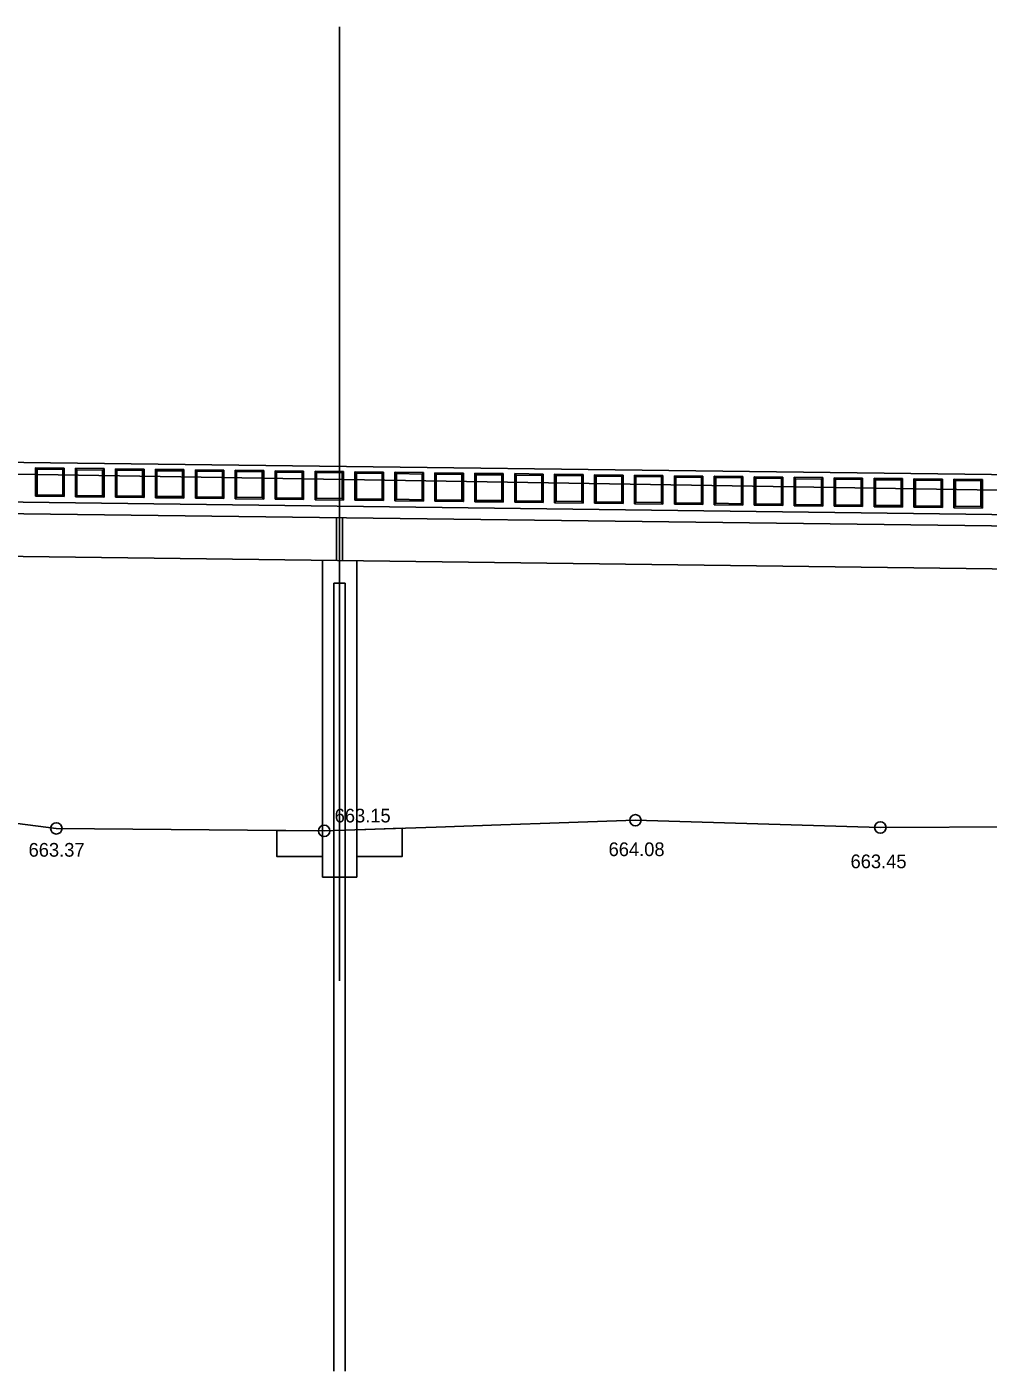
# Model space of a CAD drawing. Extents: x -845213 to 595816, y -257022 to 229056.
# Drawn here: x 595478.6 to 595562.8, y 228642.7 to 228760.5 of the extents above; entities that cross this region are included whole.
import ezdxf

# ---------------------------------------------------------------- set-up
doc = ezdxf.new("R2010")
doc.units = 0
for name, color, linetype in [('B_CL', 7, 'Continuous'), ('B_CONC', 7, 'Continuous'), ('B_CONC_HIDDEN', 7, 'Continuous'), ('B_MISC', 7, 'Continuous'), ('B_PATTERN', 7, 'Continuous'), ('B_PILES_HIDDEN', 7, 'Continuous'), ('B_SCREEN', 7, 'Continuous'), ('E_STRUCT', 7, 'Continuous'), ('P_E_PROF', 7, 'Continuous'), ('P_PROF', 7, 'Continuous')]:
    doc.layers.add(name, color=color, linetype=linetype)

msp = doc.modelspace()

# ---------------------------------------------------------------- linework, layer by layer
at = {"layer": 'B_CL'}
msp.add_line((595505.96, 228676.87), (595505.96, 228760.49), dxfattribs=at)
at = {"layer": 'B_CONC'}
for p, q in [((595399.25, 228723.31), (595719.75, 228719.29)), ((595421.62, 228718.53), (595696.95, 228715.07)), ((595505.69, 228713.72), (595505.69, 228717.47)), ((595506.23, 228713.72), (595506.23, 228717.47)), ((595417.81, 228714.82), (595700.75, 228711.28)), ((595504.46, 228687.36), (595504.46, 228713.74)), ((595507.46, 228687.45), (595507.46, 228713.7))]:
    msp.add_line(p, q, dxfattribs=at)
at = {"layer": 'B_CONC_HIDDEN'}
for p, q in [((595504.46, 228690.02), (595504.46, 228685.97)), ((595507.46, 228690.12), (595507.46, 228685.97)), ((595504.46, 228685.97), (595507.46, 228685.97))]:
    msp.add_line(p, q, dxfattribs=at)
at = {"layer": 'B_MISC'}
for centre in [(595531.89, 228690.95), (595481.13, 228690.24), (595504.61, 228690.02), (595553.36, 228690.32)]:
    msp.add_circle(centre, 0.5, dxfattribs=at)
at = {"layer": 'B_PATTERN'}
for points in [[(595507.46, 228687.79), (595507.46, 228690.12), (595511.46, 228690.25), (595511.46, 228687.79)], [(595500.46, 228690.06), (595500.46, 228687.79), (595504.46, 228687.79), (595504.46, 228690.02), (595504.46, 228690.02)]]:
    msp.add_lwpolyline(points, close=True, dxfattribs=at)
at = {"layer": 'B_PILES_HIDDEN'}
for p, q in [((595505.46, 228711.72), (595505.46, 228642.67)), ((595505.46, 228711.72), (595506.46, 228711.72)), ((595506.46, 228711.72), (595506.46, 228642.67))]:
    msp.add_line(p, q, dxfattribs=at)
at = {"layer": 'B_SCREEN'}
for p, q in [((595479.32, 228719.35), (595479.32, 228721.85)), ((595479.32, 228721.85), (595481.82, 228721.82)), ((595479.44, 228721.73), (595479.32, 228721.85)), ((595479.44, 228721.73), (595481.69, 228721.7)), ((595479.44, 228719.48), (595479.44, 228721.73)), ((595481.69, 228721.7), (595481.82, 228721.82)), ((595481.69, 228719.45), (595481.69, 228721.7)), ((595481.82, 228719.32), (595481.82, 228721.82)), ((595482.82, 228719.31), (595482.82, 228721.81)), ((595482.82, 228721.81), (595485.32, 228721.78)), ((595482.94, 228721.68), (595482.82, 228721.81)), ((595482.94, 228721.68), (595485.19, 228721.65)), ((595482.94, 228719.43), (595482.94, 228721.68)), ((595485.19, 228721.65), (595485.32, 228721.78)), ((595485.19, 228719.4), (595485.19, 228721.65)), ((595485.32, 228719.28), (595485.32, 228721.78)), ((595486.32, 228719.26), (595486.32, 228721.76)), ((595486.32, 228721.76), (595488.82, 228721.73)), ((595486.44, 228721.64), (595486.32, 228721.76)), ((595486.44, 228721.64), (595488.69, 228721.61)), ((595486.44, 228719.39), (595486.44, 228721.64)), ((595488.69, 228721.61), (595488.82, 228721.73)), ((595488.69, 228719.36), (595488.69, 228721.61)), ((595488.82, 228719.23), (595488.82, 228721.73)), ((595489.82, 228719.22), (595489.82, 228721.72)), ((595489.82, 228721.72), (595492.32, 228721.69)), ((595489.94, 228721.59), (595489.82, 228721.72)), ((595489.94, 228721.59), (595492.19, 228721.57)), ((595489.94, 228719.34), (595489.94, 228721.59)), ((595492.19, 228721.57), (595492.32, 228721.69)), ((595492.19, 228719.32), (595492.19, 228721.57)), ((595492.32, 228719.19), (595492.32, 228721.69)), ((595493.32, 228719.18), (595493.32, 228721.68)), ((595493.32, 228721.68), (595495.82, 228721.65)), ((595493.44, 228721.55), (595493.32, 228721.68)), ((595493.44, 228721.55), (595495.69, 228721.52)), ((595493.44, 228719.3), (595493.44, 228721.55)), ((595495.69, 228721.52), (595495.82, 228721.65)), ((595495.69, 228719.27), (595495.69, 228721.52)), ((595495.82, 228719.15), (595495.82, 228721.65)), ((595496.82, 228719.13), (595496.82, 228721.63)), ((595496.82, 228721.63), (595499.31, 228721.6)), ((595496.94, 228721.51), (595496.82, 228721.63)), ((595496.94, 228721.51), (595499.19, 228721.48)), ((595496.94, 228719.26), (595496.94, 228721.51)), ((595499.19, 228721.48), (595499.31, 228721.6)), ((595499.19, 228719.23), (595499.19, 228721.48)), ((595499.31, 228719.1), (595499.31, 228721.6)), ((595500.31, 228719.09), (595500.31, 228721.59)), ((595500.31, 228721.59), (595502.81, 228721.56)), ((595500.44, 228721.46), (595500.31, 228721.59)), ((595500.44, 228721.46), (595502.69, 228721.43)), ((595500.44, 228719.21), (595500.44, 228721.46)), ((595502.69, 228721.43), (595502.81, 228721.56)), ((595502.69, 228719.18), (595502.69, 228721.43)), ((595502.81, 228719.06), (595502.81, 228721.56)), ((595503.81, 228719.05), (595503.81, 228721.55)), ((595503.81, 228721.55), (595506.31, 228721.51)), ((595503.94, 228721.42), (595503.81, 228721.55)), ((595503.94, 228721.42), (595506.19, 228721.39)), ((595503.94, 228719.17), (595503.94, 228721.42)), ((595506.19, 228721.39), (595506.31, 228721.51)), ((595506.19, 228719.14), (595506.19, 228721.39)), ((595506.31, 228719.01), (595506.31, 228721.51)), ((595507.31, 228719), (595507.31, 228721.5)), ((595507.31, 228721.5), (595509.81, 228721.47)), ((595507.44, 228721.37), (595507.31, 228721.5)), ((595507.44, 228721.37), (595509.69, 228721.35)), ((595507.44, 228719.13), (595507.44, 228721.37)), ((595509.69, 228721.35), (595509.81, 228721.47)), ((595509.69, 228719.1), (595509.69, 228721.35)), ((595509.81, 228718.97), (595509.81, 228721.47)), ((595510.81, 228718.96), (595510.81, 228721.46)), ((595510.81, 228721.46), (595513.31, 228721.43)), ((595510.94, 228721.33), (595510.81, 228721.46)), ((595510.94, 228721.33), (595513.19, 228721.3)), ((595510.94, 228719.08), (595510.94, 228721.33)), ((595513.19, 228721.3), (595513.31, 228721.43)), ((595513.19, 228719.05), (595513.19, 228721.3)), ((595513.31, 228718.93), (595513.31, 228721.43)), ((595514.31, 228718.91), (595514.31, 228721.41)), ((595514.31, 228721.41), (595516.81, 228721.38)), ((595514.44, 228721.29), (595514.31, 228721.41)), ((595514.44, 228721.29), (595516.69, 228721.26)), ((595514.44, 228719.04), (595514.44, 228721.29)), ((595516.69, 228721.26), (595516.81, 228721.38)), ((595516.69, 228719.01), (595516.69, 228721.26)), ((595516.81, 228718.88), (595516.81, 228721.38)), ((595517.81, 228718.87), (595517.81, 228721.37)), ((595517.81, 228721.37), (595520.31, 228721.34)), ((595517.94, 228721.24), (595517.81, 228721.37)), ((595517.94, 228721.24), (595520.19, 228721.22)), ((595517.94, 228718.99), (595517.94, 228721.24)), ((595520.19, 228721.22), (595520.31, 228721.34)), ((595520.19, 228718.97), (595520.19, 228721.22)), ((595520.31, 228718.84), (595520.31, 228721.34)), ((595521.31, 228718.83), (595521.31, 228721.33)), ((595521.31, 228721.33), (595523.81, 228721.29)), ((595521.44, 228721.2), (595521.31, 228721.33)), ((595521.44, 228721.2), (595523.69, 228721.17)), ((595521.44, 228718.95), (595521.44, 228721.2)), ((595523.69, 228721.17), (595523.81, 228721.29)), ((595523.69, 228718.92), (595523.69, 228721.17)), ((595523.81, 228718.79), (595523.81, 228721.29)), ((595524.81, 228718.78), (595524.81, 228721.28)), ((595524.81, 228721.28), (595527.31, 228721.25)), ((595524.94, 228721.16), (595524.81, 228721.28)), ((595524.94, 228721.16), (595527.19, 228721.13)), ((595524.94, 228718.91), (595524.94, 228721.16)), ((595527.19, 228721.13), (595527.31, 228721.25)), ((595527.19, 228718.88), (595527.19, 228721.13)), ((595527.31, 228718.75), (595527.31, 228721.25)), ((595528.31, 228718.74), (595528.31, 228721.24)), ((595528.31, 228721.24), (595530.81, 228721.21)), ((595528.44, 228721.11), (595528.31, 228721.24)), ((595528.44, 228721.11), (595530.69, 228721.08)), ((595528.44, 228718.86), (595528.44, 228721.11)), ((595530.69, 228721.08), (595530.81, 228721.21)), ((595530.69, 228718.83), (595530.69, 228721.08)), ((595530.81, 228718.71), (595530.81, 228721.21)), ((595531.81, 228718.69), (595531.81, 228721.19)), ((595531.81, 228721.19), (595534.31, 228721.16)), ((595531.94, 228721.07), (595531.81, 228721.19)), ((595531.94, 228721.07), (595534.19, 228721.04)), ((595531.94, 228718.82), (595531.94, 228721.07)), ((595534.19, 228721.04), (595534.31, 228721.16)), ((595534.19, 228718.79), (595534.19, 228721.04)), ((595534.31, 228718.66), (595534.31, 228721.16)), ((595535.31, 228718.65), (595535.31, 228721.15)), ((595535.31, 228721.15), (595537.81, 228721.12)), ((595535.44, 228721.02), (595535.31, 228721.15)), ((595535.44, 228721.02), (595537.69, 228721)), ((595535.44, 228718.77), (595535.44, 228721.02)), ((595537.69, 228721), (595537.81, 228721.12)), ((595537.69, 228718.75), (595537.69, 228721)), ((595537.81, 228718.62), (595537.81, 228721.12)), ((595538.81, 228718.61), (595538.81, 228721.11)), ((595538.81, 228721.11), (595541.31, 228721.08)), ((595538.94, 228720.98), (595538.81, 228721.11)), ((595538.94, 228720.98), (595541.19, 228720.95)), ((595538.94, 228718.73), (595538.94, 228720.98)), ((595541.19, 228720.95), (595541.31, 228721.08)), ((595541.19, 228718.7), (595541.19, 228720.95)), ((595541.31, 228718.58), (595541.31, 228721.08)), ((595542.31, 228718.56), (595542.31, 228721.06)), ((595542.31, 228721.06), (595544.81, 228721.03)), ((595542.44, 228720.94), (595542.31, 228721.06)), ((595542.44, 228720.94), (595544.69, 228720.91)), ((595542.44, 228718.69), (595542.44, 228720.94)), ((595544.69, 228720.91), (595544.81, 228721.03)), ((595544.69, 228718.66), (595544.69, 228720.91)), ((595544.81, 228718.53), (595544.81, 228721.03)), ((595545.81, 228718.52), (595545.81, 228721.02)), ((595545.81, 228721.02), (595548.31, 228720.99)), ((595545.94, 228720.89), (595545.81, 228721.02)), ((595545.94, 228720.89), (595548.19, 228720.86)), ((595545.94, 228718.64), (595545.94, 228720.89)), ((595548.19, 228720.86), (595548.31, 228720.99)), ((595548.31, 228718.49), (595548.31, 228720.99)), ((595549.31, 228718.47), (595549.31, 228720.97)), ((595549.31, 228720.97), (595551.81, 228720.94)), ((595549.44, 228720.85), (595549.31, 228720.97)), ((595551.69, 228720.82), (595551.81, 228720.94)), ((595551.81, 228718.44), (595551.81, 228720.94)), ((595552.81, 228718.43), (595552.81, 228720.93)), ((595552.81, 228720.93), (595555.31, 228720.9)), ((595552.94, 228720.8), (595552.81, 228720.93)), ((595555.19, 228720.78), (595555.31, 228720.9)), ((595555.31, 228718.4), (595555.31, 228720.9)), ((595556.31, 228718.39), (595556.31, 228720.89)), ((595556.31, 228720.89), (595558.81, 228720.86)), ((595556.44, 228720.76), (595556.31, 228720.89)), ((595548.19, 228718.61), (595548.19, 228720.86)), ((595549.44, 228720.85), (595551.69, 228720.82)), ((595549.44, 228718.6), (595549.44, 228720.85)), ((595551.69, 228718.57), (595551.69, 228720.82)), ((595552.94, 228720.8), (595555.19, 228720.78)), ((595552.94, 228718.55), (595552.94, 228720.8)), ((595555.19, 228718.53), (595555.19, 228720.78)), ((595556.44, 228720.76), (595558.69, 228720.73)), ((595556.44, 228718.51), (595556.44, 228720.76)), ((595558.69, 228720.73), (595558.81, 228720.86)), ((595558.69, 228718.48), (595558.69, 228720.73)), ((595558.81, 228718.36), (595558.81, 228720.86)), ((595559.81, 228718.34), (595559.81, 228720.84)), ((595559.81, 228720.84), (595562.31, 228720.81)), ((595559.94, 228720.72), (595559.81, 228720.84)), ((595559.94, 228720.72), (595562.18, 228720.69)), ((595559.94, 228718.47), (595559.94, 228720.72)), ((595562.18, 228720.69), (595562.31, 228720.81)), ((595562.18, 228718.44), (595562.18, 228720.69)), ((595562.31, 228718.31), (595562.31, 228720.81)), ((595479.32, 228719.35), (595479.44, 228719.48)), ((595479.32, 228719.35), (595481.82, 228719.32)), ((595479.44, 228719.48), (595481.69, 228719.45)), ((595481.69, 228719.45), (595481.82, 228719.32)), ((595482.82, 228719.31), (595482.94, 228719.43)), ((595482.82, 228719.31), (595485.32, 228719.28)), ((595482.94, 228719.43), (595485.19, 228719.4)), ((595485.19, 228719.4), (595485.32, 228719.28)), ((595486.32, 228719.26), (595486.44, 228719.39)), ((595486.32, 228719.26), (595488.82, 228719.23)), ((595486.44, 228719.39), (595488.69, 228719.36)), ((595488.69, 228719.36), (595488.82, 228719.23)), ((595489.82, 228719.22), (595489.94, 228719.34)), ((595489.82, 228719.22), (595492.32, 228719.19)), ((595489.94, 228719.34), (595492.19, 228719.32)), ((595492.19, 228719.32), (595492.32, 228719.19)), ((595493.32, 228719.18), (595493.44, 228719.3)), ((595493.32, 228719.18), (595495.82, 228719.15)), ((595493.44, 228719.3), (595495.69, 228719.27)), ((595495.69, 228719.27), (595495.82, 228719.15)), ((595496.82, 228719.13), (595496.94, 228719.26)), ((595496.82, 228719.13), (595499.31, 228719.1)), ((595496.94, 228719.26), (595499.19, 228719.23)), ((595499.19, 228719.23), (595499.31, 228719.1)), ((595500.31, 228719.09), (595500.44, 228719.21)), ((595500.31, 228719.09), (595502.81, 228719.06)), ((595500.44, 228719.21), (595502.69, 228719.18)), ((595502.69, 228719.18), (595502.81, 228719.06)), ((595503.81, 228719.05), (595503.94, 228719.17)), ((595503.81, 228719.05), (595506.31, 228719.01)), ((595503.94, 228719.17), (595506.19, 228719.14)), ((595506.19, 228719.14), (595506.31, 228719.01)), ((595507.31, 228719), (595507.44, 228719.13)), ((595507.31, 228719), (595509.81, 228718.97)), ((595507.44, 228719.13), (595509.69, 228719.1)), ((595509.69, 228719.1), (595509.81, 228718.97)), ((595510.81, 228718.96), (595510.94, 228719.08)), ((595510.81, 228718.96), (595513.31, 228718.93)), ((595510.94, 228719.08), (595513.19, 228719.05)), ((595513.19, 228719.05), (595513.31, 228718.93)), ((595514.31, 228718.91), (595514.44, 228719.04)), ((595514.31, 228718.91), (595516.81, 228718.88)), ((595514.44, 228719.04), (595516.69, 228719.01)), ((595516.69, 228719.01), (595516.81, 228718.88)), ((595517.81, 228718.87), (595517.94, 228718.99)), ((595517.81, 228718.87), (595520.31, 228718.84)), ((595517.94, 228718.99), (595520.19, 228718.97)), ((595520.19, 228718.97), (595520.31, 228718.84)), ((595521.31, 228718.83), (595521.44, 228718.95)), ((595521.31, 228718.83), (595523.81, 228718.79)), ((595521.44, 228718.95), (595523.69, 228718.92)), ((595523.69, 228718.92), (595523.81, 228718.79)), ((595524.81, 228718.78), (595524.94, 228718.91)), ((595524.81, 228718.78), (595527.31, 228718.75)), ((595524.94, 228718.91), (595527.19, 228718.88)), ((595527.19, 228718.88), (595527.31, 228718.75)), ((595528.31, 228718.74), (595528.44, 228718.86)), ((595528.31, 228718.74), (595530.81, 228718.71)), ((595528.44, 228718.86), (595530.69, 228718.83)), ((595530.69, 228718.83), (595530.81, 228718.71)), ((595531.81, 228718.69), (595531.94, 228718.82)), ((595531.81, 228718.69), (595534.31, 228718.66)), ((595531.94, 228718.82), (595534.19, 228718.79)), ((595534.19, 228718.79), (595534.31, 228718.66)), ((595535.31, 228718.65), (595535.44, 228718.77)), ((595535.31, 228718.65), (595537.81, 228718.62)), ((595535.44, 228718.77), (595537.69, 228718.75)), ((595537.69, 228718.75), (595537.81, 228718.62)), ((595538.81, 228718.61), (595538.94, 228718.73)), ((595538.81, 228718.61), (595541.31, 228718.58)), ((595538.94, 228718.73), (595541.19, 228718.7)), ((595541.19, 228718.7), (595541.31, 228718.58)), ((595542.31, 228718.56), (595542.44, 228718.69)), ((595542.31, 228718.56), (595544.81, 228718.53)), ((595542.44, 228718.69), (595544.69, 228718.66)), ((595544.69, 228718.66), (595544.81, 228718.53)), ((595545.81, 228718.52), (595545.94, 228718.64)), ((595545.81, 228718.52), (595548.31, 228718.49)), ((595545.94, 228718.64), (595548.19, 228718.61)), ((595548.19, 228718.61), (595548.31, 228718.49)), ((595549.31, 228718.47), (595549.44, 228718.6)), ((595549.44, 228718.6), (595551.69, 228718.57)), ((595551.69, 228718.57), (595551.81, 228718.44)), ((595552.81, 228718.43), (595552.94, 228718.55)), ((595552.94, 228718.55), (595555.19, 228718.53)), ((595555.19, 228718.53), (595555.31, 228718.4)), ((595549.31, 228718.47), (595551.81, 228718.44)), ((595552.81, 228718.43), (595555.31, 228718.4)), ((595556.31, 228718.39), (595556.44, 228718.51)), ((595556.31, 228718.39), (595558.81, 228718.36)), ((595556.44, 228718.51), (595558.69, 228718.48)), ((595558.69, 228718.48), (595558.81, 228718.36)), ((595559.81, 228718.34), (595559.94, 228718.47)), ((595559.81, 228718.34), (595562.31, 228718.31)), ((595559.94, 228718.47), (595562.18, 228718.44)), ((595562.18, 228718.44), (595562.31, 228718.31))]:
    msp.add_line(p, q, dxfattribs=at)
at = {"layer": 'E_STRUCT'}
msp.add_line((595399.35, 228722.55), (595731.51, 228717.17), dxfattribs=at)
at = {"layer": 'P_E_PROF'}
for p, q in [((595470, 228691.63), (595481.13, 228690.24)), ((595481.13, 228690.24), (595504.61, 228690.02)), ((595504.61, 228690.02), (595514.42, 228690.35)), ((595514.42, 228690.35), (595520.09, 228690.55)), ((595520.09, 228690.55), (595523.54, 228690.67)), ((595523.54, 228690.67), (595531.89, 228690.95)), ((595531.89, 228690.95), (595553.36, 228690.32)), ((595553.36, 228690.32), (595569.07, 228690.38))]:
    msp.add_line(p, q, dxfattribs=at)
at = {"layer": 'P_PROF'}
msp.add_line((595315.56, 228720.86), (595815.56, 228714.59), dxfattribs=at)

# ---------------------------------------------------------------- texts
at = {"layer": 'B_MISC'}
for s, p in [('663.15', (595505.53, 228690.76)), ('663.37', (595478.7, 228687.76)), ('664.08', (595529.54, 228687.81)), ('663.45', (595550.75, 228686.75))]:
    msp.add_text(s, height=1.2, dxfattribs=at).set_placement(p)

doc.saveas('drawing.dxf')
